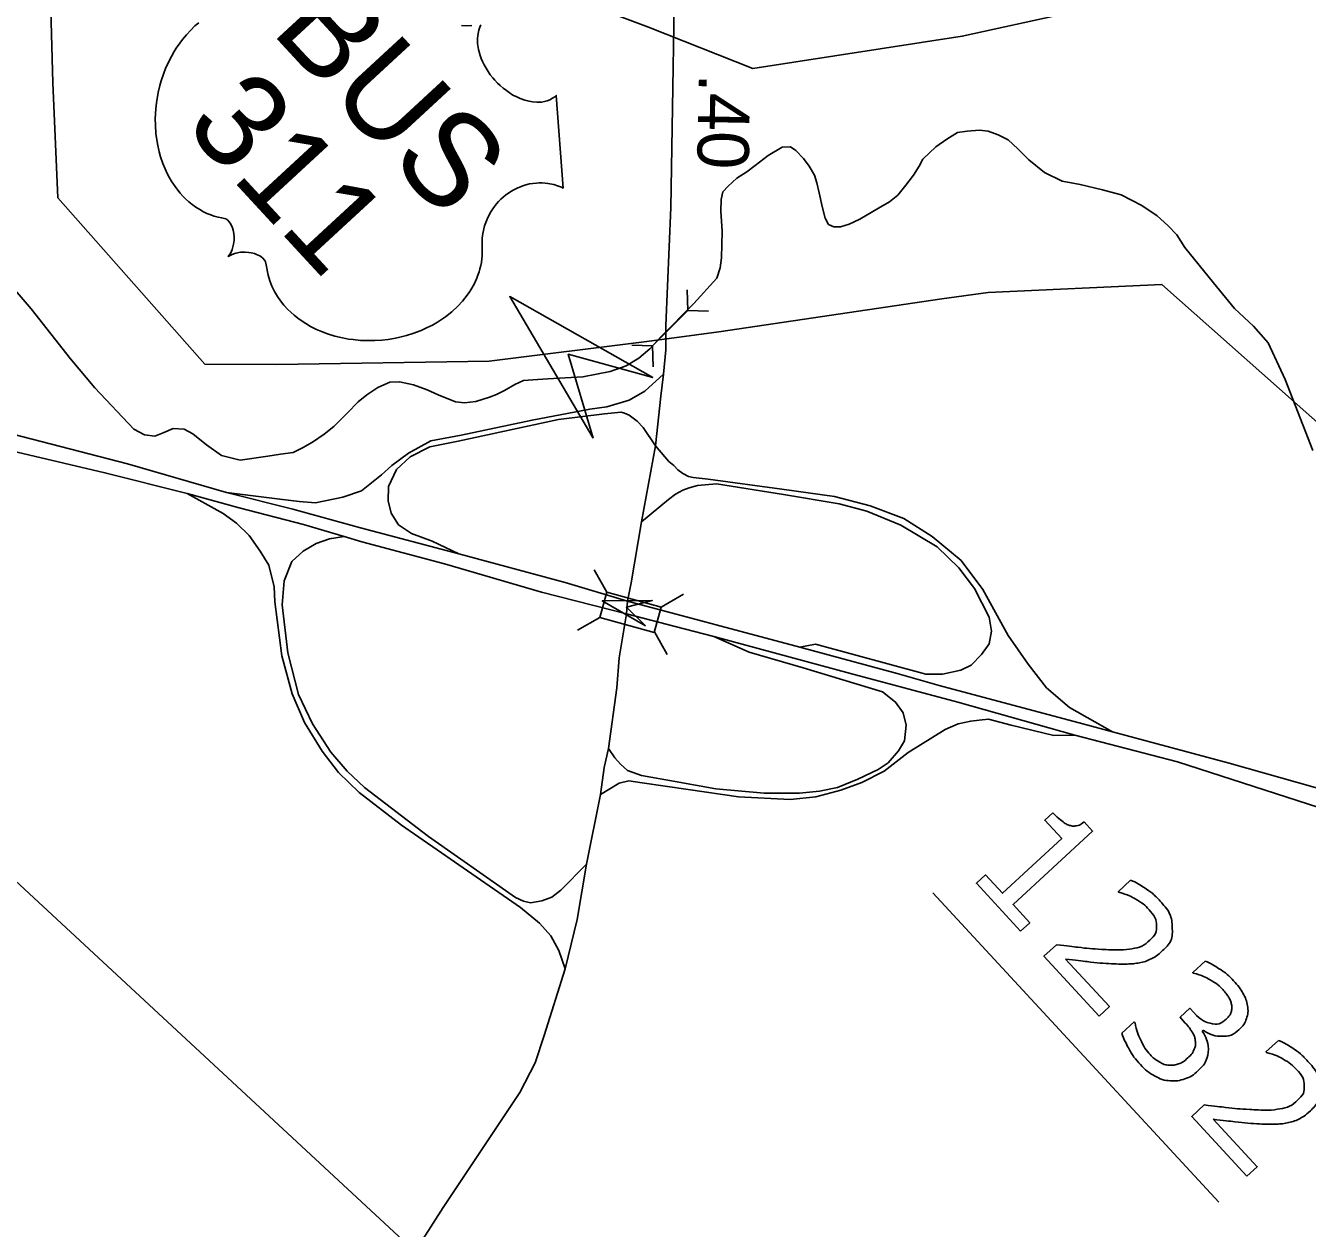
# Model space of a CAD drawing. Extents: x 1695041 to 1706254, y 786537 to 798223.
# Drawn here: x 1703287.1 to 1703431.2, y 796861.2 to 796996.4 of the extents above; entities that cross this region are included whole.
import ezdxf

# ---------------------------------------------------------------- set-up
doc = ezdxf.new("R2010")
doc.units = 0
for name, color, linetype in [('Default', 7, 'Continuous'), ('Old_Level_1', 7, 'Continuous'), ('Old_Level_27', 7, 'Continuous'), ('Old_Level_29', 7, 'Continuous'), ('Old_Level_30', 7, 'Continuous'), ('Old_Level_47', 7, 'Continuous')]:
    doc.layers.add(name, color=color, linetype=linetype)

msp = doc.modelspace()

# ---------------------------------------------------------------- linework, layer by layer
at = {"layer": 'Default'}
for p, q in [((1703361.47, 796966.73), (1703361.54, 796964.38)), ((1703361.54, 796964.38), (1703357.59, 796960.43)), ((1703363.88, 796964.32), (1703361.54, 796964.38)), ((1703355.25, 796960.49), (1703357.59, 796960.43)), ((1703357.66, 796958.08), (1703357.59, 796960.43)), ((1703351.01, 796935.26), (1703352.45, 796932.75)), ((1703358.57, 796931.06), (1703361.08, 796932.5)), ((1703349.15, 796928.45), (1703351.67, 796929.89)), ((1703357.8, 796928.27), (1703359.24, 796925.75)), ((1703389.12, 796898.96), (1703421.24, 796864.17))]:
    msp.add_line(p, q, dxfattribs=at)
for points in [[(1703291.97, 797015.19), (1703324.69, 797005.69), (1703340.9, 797002.01), (1703346.94, 797000.11), (1703357.14, 796996.22), (1703368.85, 796991.59), (1703392.4, 796995.22), (1703415.7, 797000.36), (1703437.39, 797006.05), (1703475.08, 797015.18), (1703510.21, 797012.82), (1703534.98, 797011.35), (1703569.35, 797009.42), (1703597.22, 797007.38), (1703614.23, 797006.26), (1703657.83, 797003.31), (1703684.12, 797001.47)], [(1703289.7, 797006.43), (1703290.17, 796989.97), (1703290.72, 796977.07), (1703307.24, 796958.38), (1703315.35, 796958.33), (1703339.23, 796958.68), (1703356.95, 796960.92), (1703365.05, 796961.98), (1703390.1, 796965.72), (1703395.31, 796966.42), (1703414.85, 796967.32), (1703433.69, 796950.61)], [(1703338.3, 796996.48), (1703338.19, 796996.24), (1703338.05, 796995.88), (1703337.97, 796995.54), (1703337.9, 796994.98), (1703337.9, 796994.67), (1703337.91, 796994.4), (1703338.01, 796993.74), (1703338.21, 796993.04), (1703338.32, 796992.71), (1703338.46, 796992.39), (1703338.65, 796992), (1703338.87, 796991.62), (1703339.1, 796991.25), (1703339.35, 796990.89), (1703339.63, 796990.54), (1703339.86, 796990.27), (1703340.17, 796989.95), (1703340.46, 796989.66), (1703340.78, 796989.39), (1703341.16, 796989.1), (1703341.47, 796988.88), (1703341.9, 796988.61), (1703342.32, 796988.39), (1703342.7, 796988.22), (1703343.24, 796988.03), (1703343.71, 796987.9), (1703344.09, 796987.84), (1703344.57, 796987.8), (1703345.09, 796987.82), (1703345.43, 796987.87), (1703345.74, 796987.96), (1703346.06, 796988.08), (1703346.35, 796988.24), (1703346.59, 796988.41), (1703346.77, 796988.57), (1703347.53, 796978.15), (1703347.35, 796978.24), (1703346.89, 796978.42), (1703346.5, 796978.54), (1703345.82, 796978.68), (1703345.5, 796978.71), (1703345.17, 796978.74), (1703344.84, 796978.74), (1703344.54, 796978.72), (1703344.14, 796978.68), (1703343.76, 796978.61), (1703343.35, 796978.52), (1703343.02, 796978.42), (1703342.36, 796978.15), (1703341.98, 796977.96), (1703341.67, 796977.78), (1703341.07, 796977.36), (1703340.79, 796977.14), (1703340.54, 796976.9), (1703340.29, 796976.65), (1703340.06, 796976.38), (1703339.83, 796976.09), (1703339.64, 796975.83), (1703339.42, 796975.49), (1703339.18, 796975.08), (1703338.98, 796974.65), (1703338.71, 796973.9), (1703338.51, 796973.05), (1703338.44, 796972.53), (1703338.42, 796972.04), (1703338.45, 796971.38), (1703338.45, 796971.02), (1703338.44, 796970.58), (1703338.35, 796969.8), (1703338.28, 796969.45), (1703338.19, 796969.09), (1703338.09, 796968.73), (1703337.96, 796968.35), (1703337.84, 796968.03), (1703337.52, 796967.34), (1703337.17, 796966.73), (1703336.97, 796966.41), (1703336.48, 796965.76), (1703336.23, 796965.45), (1703335.7, 796964.87), (1703335.01, 796964.23), (1703334.3, 796963.67), (1703333.41, 796963.09), (1703332.86, 796962.76), (1703332.18, 796962.43), (1703331.57, 796962.15), (1703330.63, 796961.79), (1703329.91, 796961.58), (1703329.04, 796961.36), (1703328.49, 796961.25), (1703327.88, 796961.15), (1703327.16, 796961.07), (1703326.35, 796961.01), (1703325.46, 796961.01), (1703324.77, 796961.03), (1703323.92, 796961.12), (1703323.42, 796961.18), (1703322.75, 796961.31), (1703321.87, 796961.52), (1703321.05, 796961.77), (1703320.38, 796962.02), (1703319.82, 796962.26), (1703319.13, 796962.61), (1703318.07, 796963.27), (1703317.7, 796963.53), (1703317.29, 796963.86), (1703316.93, 796964.19), (1703316.58, 796964.51), (1703316.15, 796964.98), (1703315.76, 796965.48), (1703315.42, 796965.98), (1703315.09, 796966.52), (1703314.79, 796967.13), (1703314.56, 796967.72), (1703314.37, 796968.36), (1703314.15, 796969.54), (1703314.07, 796969.86), (1703313.99, 796970.01), (1703313.74, 796970.31), (1703313.43, 796970.53), (1703313.07, 796970.7), (1703312.83, 796970.79), (1703312.48, 796970.87), (1703312.18, 796970.92), (1703311.8, 796970.94), (1703311.5, 796970.94), (1703311.28, 796970.93), (1703310.75, 796970.83), (1703310.53, 796970.76), (1703310.26, 796970.65), (1703309.89, 796970.45), (1703310.18, 796970.89), (1703310.33, 796971.23), (1703310.42, 796971.55), (1703310.49, 796971.86), (1703310.54, 796972.29), (1703310.55, 796972.64), (1703310.52, 796973.04), (1703310.44, 796973.42), (1703310.36, 796973.7), (1703310.27, 796973.94), (1703310.12, 796974.21), (1703309.97, 796974.4), (1703309.83, 796974.54), (1703309.6, 796974.7), (1703309.16, 796974.79), (1703308.74, 796974.88), (1703308.31, 796975), (1703307.83, 796975.17), (1703307.49, 796975.31), (1703307.11, 796975.49), (1703306.68, 796975.73), (1703306.24, 796976.01), (1703305.82, 796976.32), (1703305.46, 796976.61), (1703305.09, 796976.93), (1703304.79, 796977.25), (1703304.48, 796977.59), (1703304.21, 796977.93), (1703303.91, 796978.32), (1703303.55, 796978.84), (1703303.29, 796979.29), (1703303.03, 796979.79), (1703302.78, 796980.31), (1703302.55, 796980.9), (1703302.28, 796981.67), (1703302.13, 796982.23), (1703301.92, 796983.14), (1703301.76, 796984.29), (1703301.7, 796985.22), (1703301.69, 796985.93), (1703301.74, 796987.04), (1703301.81, 796987.72), (1703302.01, 796988.88), (1703302.19, 796989.67), (1703302.35, 796990.22), (1703302.64, 796991.08), (1703302.84, 796991.59), (1703303.17, 796992.31), (1703303.49, 796992.94), (1703303.81, 796993.51), (1703304.03, 796993.86), (1703304.44, 796994.45), (1703304.74, 796994.86), (1703305.18, 796995.39), (1703305.67, 796995.91), (1703306.15, 796996.37), (1703306.57, 796996.73)], [(1703336.13, 796996.43), (1703336.73, 796996.39), (1703337.28, 796996.43)], [(1703354.67, 796930.29), (1703354.76, 796931.74)], [(1703398.97, 796894.66), (1703394.01, 796900.03), (1703395.03, 796900.97), (1703396.94, 796898.9), (1703403.59, 796905.04), (1703401.68, 796907.11), (1703402.59, 796907.95)], [(1703406.11, 796906.91), (1703407.07, 796905.88), (1703398.12, 796897.62), (1703399.99, 796895.59), (1703398.97, 796894.66)], [(1703410, 796899.01), (1703409.94, 796899.07), (1703411.34, 796900.37)], [(1703407.8, 796885.09), (1703401.59, 796891.82), (1703403, 796893.12)], [(1703404.02, 796891.5), (1703408.95, 796886.16), (1703407.8, 796885.09)], [(1703418.38, 796889.93), (1703418.32, 796890), (1703419.71, 796891.28)], [(1703417.45, 796884.35), (1703416.89, 796884.96), (1703418, 796885.97), (1703418.43, 796885.51)], [(1703410.35, 796883.17), (1703411.75, 796884.45), (1703411.84, 796884.35)], [(1703419.5, 796883.51), (1703419.4, 796883.42)], [(1703426.61, 796881.01), (1703426.55, 796881.08), (1703427.95, 796882.37)], [(1703424.42, 796867.1), (1703418.21, 796873.83), (1703419.61, 796875.12)], [(1703420.63, 796873.51), (1703425.57, 796868.16), (1703424.42, 796867.1)]]:
    msp.add_lwpolyline(points, dxfattribs=at)
for points in [[(1703350.92, 796950.03), (1703341.53, 796965.95), (1703357.62, 796956.86), (1703348.12, 796959.48)], [(1703352.45, 796932.75), (1703358.57, 796931.07), (1703357.79, 796928.21), (1703351.67, 796929.89)], [(1703356.81, 796928.97), (1703351.93, 796931.76), (1703357.56, 796931.79), (1703354.65, 796931.05)]]:
    msp.add_lwpolyline(points, close=True, dxfattribs=at)
for points in [[(1703402.59, 796907.95), (1703402.98, 796907.53), (1703403.49, 796907.11), (1703404, 796906.7), (1703404.36, 796906.57), (1703404.81, 796906.42), (1703405.23, 796906.48), (1703405.65, 796906.54), (1703406.11, 796906.91)], [(1703411.34, 796900.37), (1703412.01, 796900.11), (1703412.93, 796899.49), (1703413.86, 796898.88), (1703414.54, 796898.14), (1703415.95, 796896.61), (1703416.02, 796895.06), (1703416.08, 796893.52), (1703414.82, 796892.35), (1703414.26, 796891.83), (1703413.63, 796891.52), (1703413.01, 796891.21), (1703412.31, 796891.09), (1703411.66, 796890.97), (1703410.94, 796890.95), (1703410.21, 796890.93), (1703409.27, 796890.98), (1703407.91, 796891.05), (1703406.55, 796891.2), (1703405.19, 796891.36), (1703404.02, 796891.5)], [(1703403, 796893.12), (1703404.25, 796892.97), (1703405.5, 796892.82), (1703406.75, 796892.67), (1703407.9, 796892.61), (1703410.33, 796892.47), (1703411.49, 796892.67), (1703412.66, 796892.87), (1703413.51, 796893.65), (1703414.28, 796894.36), (1703414.25, 796895.27), (1703414.21, 796896.19), (1703413.36, 796897.11), (1703412.8, 796897.71), (1703411.93, 796898.23), (1703411.07, 796898.74), (1703410, 796899.01)], [(1703419.71, 796891.28), (1703420.38, 796891.02), (1703421.31, 796890.41), (1703422.24, 796889.8), (1703422.92, 796889.06), (1703423.59, 796888.33), (1703423.97, 796887.66), (1703424.35, 796886.98), (1703424.47, 796886.26), (1703424.59, 796885.49), (1703424.36, 796884.82), (1703424.14, 796884.15), (1703423.53, 796883.59), (1703422.7, 796882.83), (1703421.55, 796882.84), (1703420.39, 796882.86), (1703419.5, 796883.51)], [(1703418.43, 796885.51), (1703419.36, 796884.49), (1703420.35, 796884.28), (1703421.33, 796884.07), (1703422.14, 796884.82), (1703422.5, 796885.15), (1703422.63, 796885.55), (1703422.76, 796885.96), (1703422.68, 796886.39), (1703422.59, 796886.84), (1703422.36, 796887.23), (1703422.12, 796887.62), (1703421.74, 796888.03), (1703421.15, 796888.67), (1703420.27, 796889.17), (1703419.38, 796889.68), (1703418.38, 796889.93)], [(1703411.84, 796884.35), (1703411.99, 796883.44), (1703412.45, 796882.44), (1703412.91, 796881.45), (1703413.57, 796880.73), (1703413.96, 796880.31), (1703414.54, 796879.97), (1703415.11, 796879.62), (1703415.66, 796879.58), (1703416.24, 796879.55), (1703416.73, 796879.72), (1703417.22, 796879.9), (1703417.77, 796880.4), (1703418.3, 796880.9), (1703418.49, 796881.39), (1703418.69, 796881.88), (1703418.61, 796882.37), (1703418.54, 796882.86), (1703418.22, 796883.36), (1703417.91, 796883.86), (1703417.45, 796884.35)], [(1703420.08, 796881.39), (1703420.09, 796880.8), (1703419.85, 796880.2), (1703419.6, 796879.59), (1703418.91, 796878.96), (1703418.23, 796878.33), (1703417.44, 796878.05), (1703416.64, 796877.77), (1703415.81, 796877.83), (1703414.88, 796877.9), (1703414.03, 796878.37), (1703413.19, 796878.84), (1703412.44, 796879.65), (1703411.68, 796880.47), (1703411.14, 796881.46), (1703410.59, 796882.44), (1703410.35, 796883.17)], [(1703419.4, 796883.42), (1703419.65, 796883.05), (1703419.86, 796882.48), (1703420.07, 796881.91), (1703420.08, 796881.39)], [(1703427.95, 796882.37), (1703428.62, 796882.11), (1703429.54, 796881.5), (1703430.47, 796880.88), (1703431.15, 796880.14), (1703432.56, 796878.61), (1703432.63, 796877.07), (1703432.69, 796875.52), (1703431.43, 796874.36), (1703430.87, 796873.83), (1703430.25, 796873.53), (1703429.62, 796873.22), (1703428.92, 796873.09), (1703428.27, 796872.97), (1703427.55, 796872.95), (1703426.83, 796872.93), (1703425.88, 796872.98), (1703424.52, 796873.05), (1703423.16, 796873.21), (1703421.8, 796873.36), (1703420.63, 796873.51)], [(1703419.61, 796875.12), (1703420.86, 796874.97), (1703422.11, 796874.82), (1703423.36, 796874.67), (1703424.51, 796874.61), (1703426.94, 796874.47), (1703428.11, 796874.67), (1703429.27, 796874.87), (1703430.12, 796875.65), (1703430.89, 796876.36), (1703430.86, 796877.28), (1703430.82, 796878.19), (1703429.97, 796879.11), (1703429.41, 796879.72), (1703428.54, 796880.23), (1703427.68, 796880.74), (1703426.61, 796881.01)]]:
    msp.add_open_spline(points, degree=3, dxfattribs=at)
at = {"layer": 'Old_Level_1'}
msp.add_line((1703210.1, 796970.55), (1703362.1, 796829.74), dxfattribs=at)
at = {"layer": 'Old_Level_27'}
for points in [[(1703309.69, 796943.93), (1703298.55, 796947.15), (1703281.29, 796951.63), (1703268.16, 796955.39), (1703249.46, 796961.68), (1703237.53, 796965.99)], [(1703235.18, 796963.92), (1703245.21, 796960.86), (1703250.34, 796958.76), (1703267.54, 796953.92), (1703281.52, 796949.57), (1703296.03, 796946.16), (1703305.27, 796943.82)], [(1703305.27, 796943.82), (1703311.11, 796942.2), (1703318.35, 796940.33), (1703322.91, 796938.99)], [(1703335.83, 796937.06), (1703324.77, 796939.97), (1703317.14, 796942.06), (1703309.69, 796943.93)], [(1703322.91, 796938.99), (1703324.9, 796938.38), (1703334.2, 796935.94), (1703345.12, 796932.75), (1703354.67, 796930.29)], [(1703354.76, 796931.74), (1703347.76, 796933.82), (1703335.83, 796937.06)], [(1703374.15, 796926.57), (1703354.76, 796931.74)], [(1703354.67, 796930.29), (1703360.13, 796928.87), (1703364.48, 796927.74)], [(1703364.48, 796927.74), (1703379.84, 796923.59), (1703391.93, 796920.39), (1703405.06, 796916.66)], [(1703409.3, 796917.03), (1703405.98, 796917.95), (1703389.83, 796922.25), (1703385.11, 796923.58), (1703374.15, 796926.57)], [(1703521.5, 796883.15), (1703482.35, 796895.62), (1703436.05, 796909.65), (1703422.42, 796913.54), (1703409.3, 796917.03)], [(1703405.06, 796916.66), (1703416.6, 796913.66), (1703434.95, 796907.77), (1703469.02, 796897.48), (1703490.65, 796890.37), (1703508.83, 796884.48)]]:
    msp.add_lwpolyline(points, dxfattribs=at)
at = {"layer": 'Old_Level_29'}
for points in [[(1703358.82, 796957.22), (1703359.08, 796959.98), (1703359.07, 796962.7), (1703359.64, 796975.95), (1703359.85, 796987.16), (1703360.02, 796998.63), (1703360.5, 797010.45), (1703361.06, 797020.72), (1703361.07, 797025.52), (1703360.87, 797028.8)], [(1703357.93, 796949.19), (1703358.51, 796954.77), (1703358.82, 796957.22)], [(1703356.33, 796940.66), (1703357.93, 796949.19)], [(1703354.76, 796931.74), (1703355.18, 796933.78), (1703356.33, 796940.66)], [(1703352.63, 796915.16), (1703353.56, 796921.98), (1703353.85, 796925.37), (1703354.67, 796930.29)], [(1703351.73, 796910), (1703352.15, 796913.05), (1703352.63, 796915.16)], [(1703350.17, 796902.18), (1703351.73, 796910)], [(1703347.76, 796890.39), (1703349.13, 796895.96), (1703350.17, 796902.18)], [(1703307.5, 796720.88), (1703305.71, 796773.4), (1703304.31, 796793.72), (1703304.04, 796802.98), (1703304.35, 796810.77), (1703304.69, 796814.35), (1703305.1, 796817.04), (1703305.98, 796819), (1703306.98, 796821.46), (1703308.06, 796823.62), (1703310.94, 796828.2), (1703316.06, 796836.2), (1703320.95, 796843.6), (1703328.71, 796855.18), (1703334.05, 796863.57), (1703342.66, 796876.52), (1703344.39, 796879.85), (1703345.42, 796882.91), (1703347.76, 796890.39)]]:
    msp.add_lwpolyline(points, dxfattribs=at)
at = {"layer": 'Old_Level_30'}
for points in [[(1703374.55, 796981.49), (1703375.21, 796980.63), (1703375.78, 796979.59), (1703376.05, 796978.75), (1703376.33, 796977.61), (1703376.65, 796976.09), (1703376.98, 796974.78), (1703377.39, 796974.07), (1703377.97, 796973.79), (1703378.73, 796973.81), (1703379.68, 796974.08), (1703380.9, 796974.65), (1703383.01, 796975.89), (1703384.23, 796976.61), (1703385.15, 796977.37), (1703386.08, 796978.47), (1703386.92, 796979.6), (1703387.57, 796980.61), (1703387.97, 796981.4), (1703389.44, 796982.8), (1703390.66, 796983.66), (1703391.89, 796984.4), (1703392.95, 796984.54), (1703394.36, 796984.66), (1703395.33, 796984.54), (1703396.46, 796984.14), (1703397.58, 796983.57), (1703398.66, 796982.56), (1703399.91, 796981.31), (1703401.65, 796979.89), (1703403.66, 796978.94), (1703405.65, 796978.55), (1703408.19, 796977.97), (1703410.29, 796977.38), (1703412.59, 796976.19), (1703414.32, 796975.05), (1703415.51, 796973.94), (1703416.52, 796972.91), (1703417.44, 796971.46), (1703420.66, 796967.5), (1703423, 796964.62), (1703425.14, 796962.65), (1703426.79, 796960.77), (1703428.73, 796956.65), (1703431.83, 796948.66)], [(1703284.58, 796968.26), (1703287.73, 796964.58), (1703292.17, 796958.97), (1703294.88, 796955.72), (1703299.29, 796951.07), (1703300.47, 796950.41), (1703301.64, 796950.26), (1703302.58, 796950.66), (1703303.7, 796951.15), (1703304.94, 796951.07), (1703305.9, 796950.54), (1703307.44, 796949.3), (1703309.14, 796948.09), (1703311.24, 796947.56), (1703314.32, 796948.02), (1703315.78, 796948.24), (1703317.18, 796948.44), (1703318.25, 796948.95), (1703319.35, 796949.58), (1703320.69, 796950.49), (1703321.76, 796951.35), (1703323.24, 796952.87), (1703324.48, 796954.12), (1703325.48, 796954.93), (1703326.7, 796955.74), (1703328.04, 796956.34), (1703329.15, 796956.39), (1703330.7, 796956.04), (1703332.24, 796955.46), (1703333.48, 796954.92), (1703335.42, 796954.11), (1703336.44, 796954), (1703337.74, 796954.17), (1703339.25, 796954.65), (1703340.05, 796954.97), (1703340.94, 796955.4), (1703342.12, 796956.07), (1703343.08, 796956.52), (1703344.14, 796956.6), (1703345.82, 796956.72), (1703349.77, 796956.92), (1703352.81, 796957.54), (1703354.63, 796958.16), (1703356.05, 796959.02), (1703357.29, 796960.1), (1703358.57, 796961.48), (1703362.22, 796965.17), (1703364.8, 796968.01), (1703365.18, 796969.17), (1703365.35, 796970.33), (1703365.43, 796973.32), (1703365.25, 796975.54), (1703365.3, 796976.85), (1703365.5, 796977.71), (1703366.11, 796978.37), (1703367.08, 796979.27), (1703368.19, 796979.99), (1703369.14, 796980.69), (1703370.59, 796981.8), (1703372.18, 796982.74), (1703373.1, 796982.8), (1703373.7, 796982.37), (1703374.55, 796981.49)]]:
    msp.add_lwpolyline(points, dxfattribs=at)
at = {"layer": 'Old_Level_47'}
for points in [[(1703358.82, 796957.22), (1703356.72, 796955.34), (1703354.97, 796954.31), (1703352.45, 796953.55), (1703350.53, 796953.29), (1703344.05, 796952.07), (1703336.07, 796950.4), (1703332.68, 796949.75), (1703330.15, 796948.36), (1703328.27, 796946.98), (1703327.12, 796945.91), (1703324.87, 796944.11), (1703322.77, 796943.41), (1703319.69, 796942.79), (1703317.86, 796942.92), (1703315.7, 796943.2), (1703309.69, 796943.93)], [(1703335.83, 796937.06), (1703332.82, 796938.47), (1703330.48, 796939.35), (1703329.03, 796940.3), (1703328.2, 796941.62), (1703327.86, 796943.02), (1703327.92, 796944.6), (1703328.79, 796946.54), (1703330.33, 796947.96), (1703332.55, 796949.06), (1703335.74, 796949.72), (1703347.02, 796952.15), (1703352.17, 796952.79), (1703354.07, 796952.95), (1703354.45, 796952.84), (1703354.95, 796952.62), (1703355.86, 796951.95), (1703356.54, 796951.25), (1703357.93, 796949.19)], [(1703409.3, 796917.03), (1703404.47, 796919.79), (1703401.89, 796921.97), (1703399.82, 796924.63), (1703397.58, 796927.88), (1703394.72, 796933.04), (1703392.28, 796936.3), (1703389.02, 796939), (1703385.84, 796941.01), (1703382.04, 796942.45), (1703378.03, 796943.5), (1703372.12, 796944.32), (1703363.86, 796945.44), (1703362.17, 796945.61), (1703361.65, 796945.73), (1703360.99, 796946.07), (1703360.42, 796946.49), (1703359.97, 796946.98), (1703359.44, 796947.43), (1703358.96, 796947.95), (1703357.93, 796949.19)], [(1703356.33, 796940.66), (1703359.39, 796943.14), (1703360.17, 796943.77), (1703361.01, 796944.2), (1703361.7, 796944.46), (1703362.63, 796944.73), (1703364.77, 796944.91), (1703372.31, 796943.72), (1703378.56, 796942.65), (1703381.67, 796941.84), (1703385.5, 796940.25), (1703389.58, 796937.84), (1703392.01, 796935.48), (1703393.77, 796933.16), (1703395.42, 796929.94), (1703395.69, 796928.36), (1703395.43, 796926.93), (1703394.56, 796925.74), (1703393.42, 796924.55), (1703392.24, 796923.98), (1703390.17, 796923.52), (1703388.32, 796923.52), (1703375.91, 796926.88), (1703374.15, 796926.57)], [(1703305.27, 796943.82), (1703309.32, 796941.59), (1703310.82, 796940.5), (1703312.25, 796939.09), (1703313.47, 796937.36), (1703314.44, 796935.77), (1703315.06, 796933.35), (1703315.12, 796931.67), (1703315.91, 796925.57), (1703317.09, 796921.32), (1703318.45, 796918.1), (1703320.45, 796914.86), (1703322.29, 796912.46), (1703324.59, 796910.24), (1703329.35, 796906.56), (1703342.74, 796897.31), (1703344.87, 796895.54), (1703346.17, 796894.13), (1703347.07, 796892.48), (1703347.76, 796890.39)], [(1703350.17, 796902.18), (1703347.28, 796899.26), (1703346.27, 796898.46), (1703345.16, 796898.05), (1703343.86, 796897.84), (1703343.09, 796898), (1703342.2, 796898.43), (1703332.4, 796905.28), (1703325.19, 796910.79), (1703323.27, 796912.62), (1703321.41, 796914.76), (1703319.35, 796917.94), (1703317.8, 796921.23), (1703316.57, 796925.93), (1703315.94, 796931.32), (1703316.18, 796934.02), (1703317.04, 796936.18), (1703318.32, 796937.36), (1703319.77, 796938.21), (1703321.28, 796938.73), (1703322.91, 796938.99)], [(1703364.48, 796927.74), (1703368.47, 796926.01), (1703374.53, 796924.22), (1703383.45, 796921.53), (1703384.91, 796920.38), (1703385.75, 796919.18), (1703386.1, 796917.8), (1703385.9, 796916.03), (1703385.24, 796914.89), (1703384.09, 796913.57), (1703382.96, 796912.8), (1703380.66, 796911.72), (1703378.37, 796910.79), (1703376.37, 796910.39), (1703374.1, 796910.14), (1703370.14, 796910.16), (1703364.69, 796910.65), (1703360.14, 796911.45), (1703356.33, 796912.14), (1703354.78, 796912.68), (1703353.99, 796913.4), (1703353.34, 796914.11), (1703352.63, 796915.16)], [(1703351.73, 796910), (1703353.84, 796911.29), (1703354.94, 796911.52), (1703356.44, 796911.32), (1703361.6, 796910.57), (1703367.25, 796909.73), (1703373.05, 796909.43), (1703375.93, 796909.72), (1703378.77, 796910.5), (1703381.13, 796911.36), (1703383.64, 796912.63), (1703386.32, 796914.71), (1703390.49, 796917.3), (1703391.95, 796917.93), (1703393.36, 796918.26), (1703394.32, 796918.36), (1703395.35, 796918.45), (1703397.91, 796917.8), (1703402.71, 796916.64), (1703405.06, 796916.66)]]:
    msp.add_lwpolyline(points, dxfattribs=at)

# ---------------------------------------------------------------- texts
at = {"layer": 'Default'}
for s, height, rotation, p in [('BUS', 10.569, 312.7091, (1703314.56, 796995.77)), ('311', 10.569, 312.7091, (1703304.78, 796985.06)), ('.40', 5.775, 268.9189, (1703362.81, 796991.05))]:
    msp.add_text(s, height=height, rotation=rotation, dxfattribs=at).set_placement(p)

doc.saveas('drawing.dxf')
